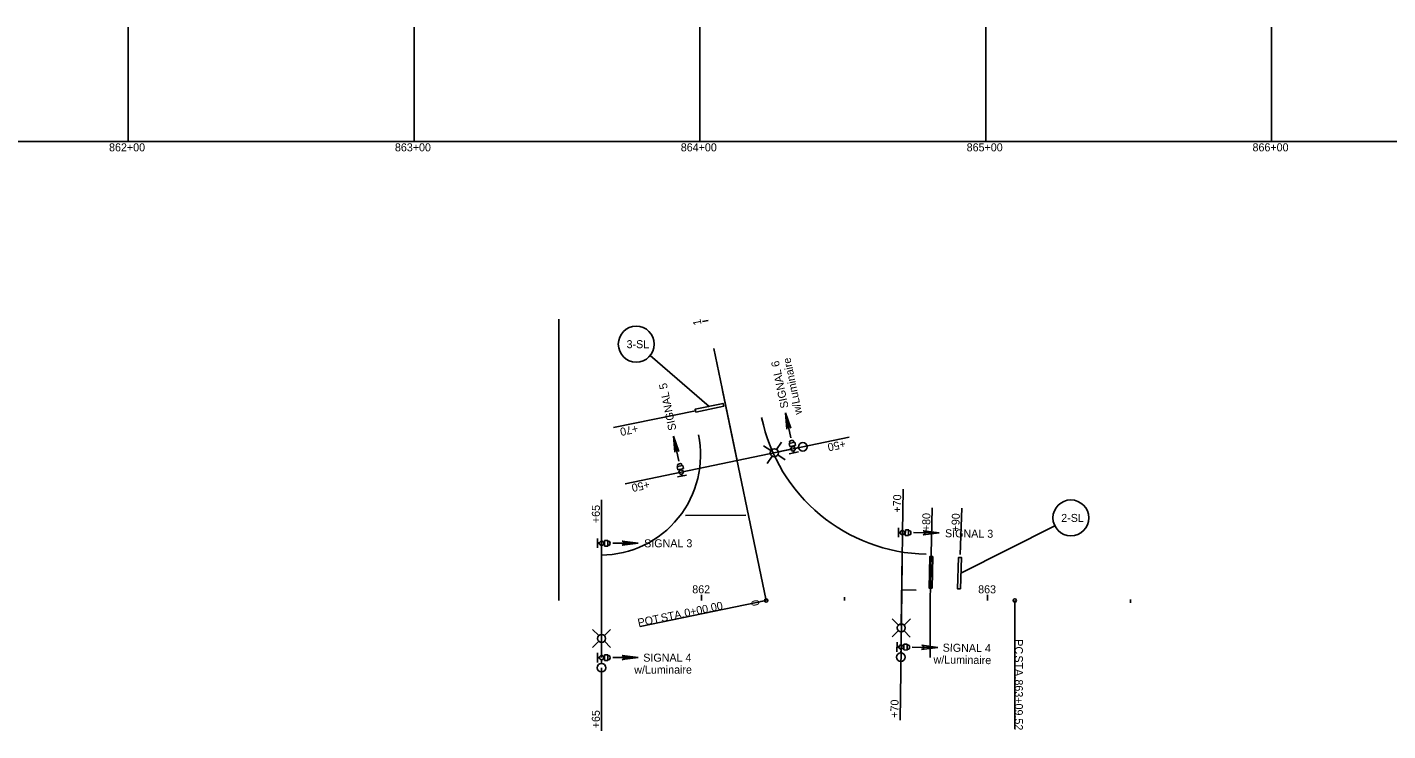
# Model space of a CAD drawing. Extents: x -1395 to 1843, y -1176 to 1887.
# Drawn here: x 1124.1 to 1600, y 505.4 to 751.4 of the extents above; entities that cross this region are included whole.
import ezdxf

# ---------------------------------------------------------------- set-up
doc = ezdxf.new("R2010")
doc.units = 0
for name, color, linetype in [('DR_P_Ditch', 7, 'Continuous'), ('DR_X_Ditch', 7, 'Continuous'), ('RW_X_Text', 7, 'Continuous'), ('SH_Major_Grid_Line', 7, 'Continuous'), ('SH_Masking', 7, 'Continuous'), ('SH_Named_Boundary', 7, 'Continuous'), ('SH_Text', 7, 'Continuous'), ('SV_X_Toe_of_Slope', 7, 'Continuous'), ('XS_P_Annotation', 7, 'Continuous'), ('XS_P_Pavt_Surface', 7, 'Continuous')]:
    doc.layers.add(name, color=color, linetype=linetype)

msp = doc.modelspace()

# ---------------------------------------------------------------- linework, layer by layer
at = {"layer": 'DR_P_Ditch'}
for points in [[(1357.95, 616.86), (1357.75, 617.84), (1367.54, 619.87), (1367.74, 618.89)], [(1440.61, 555.31), (1439.61, 555.33), (1439.84, 566.33), (1440.84, 566.31)], [(1450.54, 555), (1449.54, 555.04), (1449.93, 566.03), (1450.93, 565.99)]]:
    msp.add_lwpolyline(points, close=True, dxfattribs=at)
at = {"layer": 'DR_X_Ditch'}
for centre, radius, start, end in [((1439.77, 627.15), 60, 191.7125, 268.8811), ((1324.64, 601.84), 35, 270.365, 11.7448)]:
    msp.add_arc(centre, radius, start, end, dxfattribs=at)
at = {"layer": 'RW_X_Text'}
msp.add_line((1354.32, 580.68), (1375.51, 580.82), dxfattribs=at)
at = {"layer": 'SH_Major_Grid_Line'}
for centre in [(1337.16, 640.61), (1489.2, 579.85)]:
    msp.add_circle(centre, 6.29, dxfattribs=at)
at = {"layer": 'SH_Masking'}
for p, q in [((1382.59, 550.99), (1338.52, 541.86)), ((1469.54, 550.99), (1469.54, 505.99))]:
    msp.add_line(p, q, dxfattribs=at)
for centre in [(1382.59, 550.99), (1469.54, 550.99)]:
    msp.add_circle(centre, 0.6, dxfattribs=at)
at = {"layer": 'SH_Named_Boundary'}
for p, q in [((1310.02, 649.33), (1310.02, 550.99)), ((1364.32, 639.12), (1372.44, 599.95)), ((1382.59, 550.99), (1367.36, 624.43)), ((1357.85, 617.35), (1329.21, 611.42)), ((1352.85, 595.89), (1392.02, 604.01)), ((1440.7, 583.37), (1440.36, 567.12)), ((1451.03, 583.25), (1450.46, 567.01)), ((1430.27, 574.7), (1430.02, 554.7)), ((1325.02, 570.99), (1325.02, 530.99)), ((1430.18, 567.27), (1429.86, 542.13)), ((1430.18, 567.29), (1430.02, 554.7)), ((1440.36, 567.12), (1440.02, 550.99)), ((1430.02, 554.7), (1429.77, 534.7)), ((1430.02, 554.7), (1435.02, 554.63)), ((1440.02, 550.99), (1440.02, 530.99))]:
    msp.add_line(p, q, dxfattribs=at)
at = {"layer": 'SH_Text'}
for p, q in [((1391.23, 607.82), (1389.41, 616.58)), ((1389.87, 610.93), (1389.41, 616.58)), ((1389.41, 616.58), (1391.24, 611.22)), ((1352.01, 599.69), (1350.19, 608.45)), ((1350.65, 602.8), (1350.19, 608.45)), ((1350.19, 608.45), (1352.02, 603.08)), ((1384.28, 603.42), (1381.7, 605.11)), ((1386.22, 603.82), (1387.91, 606.4)), ((1392.57, 606.33), (1390.59, 605.92)), ((1390.59, 605.93), (1390.83, 604.8)), ((1390.79, 606.46), (1390.89, 605.99)), ((1392.8, 605.21), (1390.83, 604.8)), ((1391.77, 604.73), (1391.72, 604.98)), ((1391.96, 604.77), (1391.91, 605.02)), ((1392.2, 606.76), (1392.3, 606.28)), ((1392.57, 606.33), (1392.8, 605.21)), ((1384.68, 601.48), (1382.99, 598.9)), ((1386.62, 601.88), (1389.2, 600.19)), ((1391.28, 603.86), (1386.82, 602.93)), ((1393.92, 602.97), (1390.69, 602.3)), ((1392.21, 602.61), (1392.07, 603.26)), ((1392.4, 602.65), (1392.27, 603.3)), ((1393.99, 604.42), (1392.76, 604.17)), ((1353.4, 598.21), (1351.42, 597.8)), ((1351.42, 597.81), (1351.66, 596.68)), ((1351.62, 598.34), (1351.72, 597.87)), ((1353.63, 597.09), (1351.66, 596.68)), ((1352.6, 596.61), (1352.55, 596.86)), ((1352.8, 596.65), (1352.74, 596.9)), ((1353.04, 594.49), (1352.91, 595.14)), ((1353.03, 598.64), (1353.13, 598.16)), ((1353.24, 594.53), (1353.1, 595.18)), ((1353.4, 598.21), (1353.63, 597.09)), ((1354.75, 594.85), (1351.53, 594.18)), ((1428.84, 573.07), (1428.88, 576.36)), ((1323.61, 569.35), (1323.61, 572.64)), ((1326.03, 569.99), (1326.03, 572)), ((1327.19, 572), (1326.03, 572)), ((1327.18, 569.99), (1327.18, 572)), ((1327.67, 571.7), (1327.18, 571.7)), ((1332.23, 571.75), (1337.86, 571.05)), ((1428.86, 574.81), (1429.52, 574.8)), ((1428.86, 574.61), (1429.52, 574.6)), ((1431.02, 574.79), (1431.28, 574.78)), ((1431.02, 574.59), (1431.28, 574.58)), ((1431.27, 573.68), (1431.3, 575.69)), ((1432.42, 573.66), (1431.27, 573.68)), ((1432.45, 575.68), (1431.3, 575.69)), ((1432.42, 573.66), (1432.44, 575.68)), ((1432.91, 573.93), (1432.43, 573.93)), ((1432.93, 575.37), (1432.44, 575.37)), ((1434.16, 574.7), (1443.11, 574.59)), ((1443.11, 574.59), (1437.47, 573.96)), ((1437.49, 575.36), (1443.11, 574.59)), ((1323.61, 571.09), (1324.27, 571.09)), ((1323.61, 570.89), (1324.27, 570.89)), ((1325.77, 571.09), (1326.03, 571.09)), ((1325.77, 570.89), (1326.03, 570.89)), ((1327.18, 569.99), (1326.03, 569.99)), ((1327.67, 570.26), (1327.18, 570.26)), ((1328.91, 571.05), (1337.86, 571.05)), ((1337.86, 571.05), (1332.23, 570.35)), ((1428.87, 542.41), (1426.72, 544.62)), ((1430.85, 542.38), (1433.06, 544.54)), ((1324.03, 538.69), (1321.85, 540.87)), ((1326.01, 538.69), (1328.19, 540.87)), ((1428.85, 540.43), (1426.64, 538.27)), ((1429.77, 535.46), (1429.83, 540.01)), ((1430.83, 540.4), (1432.98, 538.19)), ((1324.03, 536.71), (1321.85, 534.53)), ((1325.02, 531.75), (1325.02, 536.3)), ((1326.01, 536.71), (1328.19, 534.53)), ((1428.34, 533.07), (1428.38, 536.36)), ((1428.35, 534.62), (1429.01, 534.61)), ((1428.36, 534.82), (1429.02, 534.81)), ((1429.74, 532.69), (1429.76, 533.94)), ((1430.51, 534.59), (1430.78, 534.59)), ((1430.52, 534.79), (1430.78, 534.79)), ((1430.76, 533.68), (1430.79, 535.69)), ((1431.91, 533.66), (1430.76, 533.68)), ((1431.95, 535.68), (1430.79, 535.69)), ((1431.91, 533.66), (1431.94, 535.68)), ((1432.4, 533.93), (1431.92, 533.93)), ((1432.42, 535.37), (1431.94, 535.37)), ((1433.66, 534.65), (1442.6, 534.54)), ((1442.6, 534.54), (1436.97, 533.9)), ((1436.99, 535.31), (1442.6, 534.54)), ((1323.61, 529.35), (1323.61, 532.64)), ((1323.61, 531.09), (1324.27, 531.09)), ((1323.61, 530.89), (1324.27, 530.89)), ((1325.02, 528.98), (1325.02, 530.24)), ((1325.77, 531.09), (1326.03, 531.09)), ((1325.77, 530.89), (1326.03, 530.89)), ((1326.03, 529.98), (1326.03, 532)), ((1327.19, 532), (1326.03, 532)), ((1327.18, 529.98), (1326.03, 529.98)), ((1327.18, 529.98), (1327.18, 532)), ((1327.67, 531.7), (1327.18, 531.7)), ((1327.67, 530.25), (1327.18, 530.25)), ((1328.91, 530.99), (1337.86, 530.99)), ((1332.23, 531.7), (1337.86, 530.99)), ((1337.86, 530.99), (1332.23, 530.29))]:
    msp.add_line(p, q, dxfattribs=at)
for centre, radius in [((1392.02, 604.01), 0.757), ((1395.46, 604.72), 1.5), ((1385.45, 602.65), 1.4), ((1352.85, 595.89), 0.757), ((1325.02, 570.99), 0.757), ((1430.27, 574.7), 0.757), ((1429.85, 541.4), 1.4), ((1325.02, 537.7), 1.4), ((1429.77, 534.7), 0.757), ((1325.02, 527.48), 1.5), ((1325.02, 530.99), 0.757), ((1429.72, 531.19), 1.5)]:
    msp.add_circle(centre, radius, dxfattribs=at)
for centre, radius, start, end in [((1390.55, 611.08), 0.703, 11.7124, 191.7124), ((1351.33, 602.94), 0.702, 11.7124, 191.7124), ((1332.23, 571.05), 0.702, 270, 90), ((1437.48, 574.66), 0.703, 269.2749, 89.2749), ((1436.98, 534.61), 0.703, 269.2749, 89.2749), ((1332.23, 530.99), 0.703, 270, 90)]:
    msp.add_arc(centre, radius, start, end, dxfattribs=at)
for centre, major_axis in [((1391.5, 606.61), (0.706, 0.146)), ((1352.33, 598.49), (0.706, 0.147)), ((1327.67, 570.98), (0.001, -0.721)), ((1432.92, 574.65), (-0.008, -0.721)), ((1432.41, 534.65), (-0.009, -0.721)), ((1327.67, 530.98), (0, -0.721))]:
    msp.add_ellipse(centre, major_axis=major_axis, ratio=0.45371, start_param=0, end_param=3.141593, dxfattribs=at)
at = {"layer": 'SV_X_Toe_of_Slope'}
for p, q in [((1159.41, 711.44), (1159.41, 751.44)), ((1259.41, 711.44), (1259.41, 751.44)), ((1359.41, 711.44), (1359.41, 751.44)), ((1459.41, 711.44), (1459.41, 751.44)), ((1559.41, 711.44), (1559.41, 751.44)), ((1059.41, 711.44), (1659.41, 711.44))]:
    msp.add_line(p, q, dxfattribs=at)
at = {"layer": 'XS_P_Annotation'}
for p, q in [((1362.29, 648.91), (1360.33, 648.5)), ((1372.44, 599.95), (1371.26, 599.71)), ((1310.02, 550.99), (1310.02, 552.19)), ((1360.02, 550.99), (1360.02, 552.99)), ((1410.02, 550.99), (1410.02, 552.19)), ((1460.02, 550.99), (1460.02, 552.99)), ((1382.59, 550.99), (1380.63, 550.59)), ((1510.01, 550.14), (1510.06, 551.33))]:
    msp.add_line(p, q, dxfattribs=at)
at = {"layer": 'XS_P_Pavt_Surface'}
for p, q in [((1342.03, 636.61), (1362.64, 618.86)), ((1392.02, 604), (1411.6, 608.06)), ((1333.27, 591.83), (1352.85, 595.89)), ((1325.02, 586.19), (1325.02, 570.99)), ((1430.46, 589.89), (1430.27, 574.7)), ((1483.54, 577.08), (1450.73, 560.5)), ((1429.76, 534.7), (1429.43, 509.13)), ((1325.01, 527.48), (1325.01, 505.42))]:
    msp.add_line(p, q, dxfattribs=at)

# ---------------------------------------------------------------- texts
at = {"layer": 'SH_Masking'}
for s, rotation, p in [(' STA. ', 11.7125, (1345.01, 543.25)), ('0+00.00', 11.7125, (1354.27, 545.16)), ('POT', 11.7125, (1337.96, 541.78)), ('PC', 270, (1469.59, 537.42)), (' STA. ', 270, (1469.59, 532.83)), ('863+09.52', 270, (1469.59, 523.38))]:
    msp.add_text(s, height=2.8, rotation=rotation, dxfattribs=at).set_placement(p)
at = {"layer": 'SH_Named_Boundary'}
for s, rotation, p in [('3-SL', 0.0561, (1333.77, 639.2)), ('SIGNAL 6', 101.7995, (1390.46, 618.5)), ('w/Luminaire', 101.7995, (1395.2, 616.34)), ('SIGNAL 5', 101.7685, (1351.22, 610.72)), ('+70', 191.7685, (1337.48, 612.52)), ('+50', 191.7685, (1410.09, 607.14)), ('+50', 191.7685, (1341.54, 592.94)), ('+70', 89.331, (1429.77, 581.7)), ('+65', 90.0561, (1324.42, 578.04)), ('+80', 88.8548, (1439.93, 575.19)), ('+90', 88.0561, (1450.15, 575.08)), ('2-SL', 0.0561, (1485.8, 578.45)), ('SIGNAL 3', 359.331, (1445.14, 573.1)), ('SIGNAL 3', 0.0561, (1339.91, 569.58)), ('SIGNAL 4', 359.362, (1444.33, 533.1)), ('w/Luminaire', 0.0871, (1336.45, 525.38)), ('SIGNAL 4', 0.0871, (1339.61, 529.58)), ('w/Luminaire', 359.362, (1441.12, 528.94)), ('+70', 89.331, (1428.85, 509.96)), ('+65', 90.0561, (1324.42, 506.29))]:
    msp.add_text(s, height=2.8, rotation=rotation, dxfattribs=at).set_placement(p)
at = {"layer": 'SV_X_Toe_of_Slope'}
for s, p in [('862+00', (1152.73, 708.04)), ('863+00', (1252.73, 708.04)), ('864+00', (1352.73, 708.04)), ('865+00', (1452.73, 708.04)), ('866+00', (1552.73, 708.04))]:
    msp.add_text(s, height=2.8, dxfattribs=at).set_placement(p)
at = {"layer": 'XS_P_Annotation'}
for s, rotation, p in [('1', 101.7125, (1360.02, 647.51)), ('862', 0, (1356.74, 553.49)), ('863', 0, (1456.75, 553.49)), ('0', 101.7125, (1380.36, 549.4))]:
    msp.add_text(s, height=2.8, rotation=rotation, dxfattribs=at).set_placement(p)

doc.saveas('drawing.dxf')
